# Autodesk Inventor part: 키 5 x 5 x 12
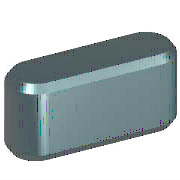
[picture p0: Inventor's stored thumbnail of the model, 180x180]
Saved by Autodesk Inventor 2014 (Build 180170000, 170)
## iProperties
Created: 2012-02
Part Number: 키 5 x 5 x 12
Material: 강철, 연강
Description: 키 및 해당 키홈
Document SubType Name: Modeling
Standard: KS B 1311
Designer: mduedu
Standards Organization: KS
Language: ko-KR
Size Designation: 5 x 5 x 12
Categories: <MemberInstance><Categories><Category DisplayName="샤프트 부품" InternalName="7f7aeb1f-a693-4053-b835-cee3144e0d98" Mnemonic="SHFT"><Category DisplayName="키" Interna
Density: 7.86 g/cm^3
Appearance: 노란색
Mass: 2.11085 g
Surface Area: 2.43471 cm^2
Volume: 0.268556 cm^3
IsCustomPart: 1
Author: mduedu
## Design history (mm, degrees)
workplane "Work Plane1"
workplane "Work Plane2"
sketch "스케치1"
  geometry: L1 (2.5, 2.5)-(9.5, 2.5); L2 (9.5, -2.5)-(2.5, -2.5); L3 (0, 9.4)-(0, -7.4) reference; L4 (-5, 0)-(30, 0) reference; L5 (12, 0)-(12, 7); A1 r 2.5 centre (2.5, 0) between (2.5, 2.5) and (2.5, -2.5); A2 r 2.5 centre (9.5, 0) between (9.5, -2.5) and (9.5, 2.5)
  constraints: 6 end point, 5 point on circle, 4 tangent, 3 point on line, 2 centre point, 1 horizontal, 1 parallel, 1 perpendicular
  dimensions: "d0" = 2.5 radius of A1 (= 0.5 x PB); "d13" = 2.5 radius of A2 (= 0.5 x PB); "d14" = 12 distance between parallel lines of L5 L3 (= NLG)
extrude "본체1" new body sketch "스케치1" taper "d3" = 0 deg; stored distance "d4" = 10
workplane "Work Plane3"
body "Solid1"
chamfer "모따기1" distance "d8" = 0.4 (= PHH); stored, may be unused: second distance "d9" = 0.4 (= PHH), angle "d15" = 45 deg
other parameters: "d1" = -3 (= -PNT), "d2" = 2 (= PH - PNT), "NLG" = 12 [user parameter; used in 3 equation terms], "PB" = 5 [user parameter; used in 2 equation terms], "PNT" = 3 [user parameter; used in 2 equation terms], "PH" = 5 [user parameter; used in 1 equation term], "PHH" = 0.4 [user parameter; used in 2 equation terms], "d10" = 0, "d16" = 0, "d17" = 0, "d18" = 0, "WDMIN" = 12 [user parameter], "PLB2" = 12 (= NLG) [user parameter], "WDMAX" = 17 [user parameter], "PLB1" = 12 (= NLG) [user parameter], "RR" = 0.16 [user parameter], "PUEB" = 2.3 [user parameter]
